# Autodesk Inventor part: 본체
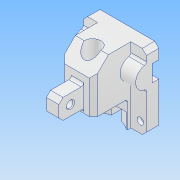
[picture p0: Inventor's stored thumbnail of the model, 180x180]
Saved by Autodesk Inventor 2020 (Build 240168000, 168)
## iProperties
Created: 2022-08
Part Number: 본체
Material: 알루미늄 6061
Document SubType Name: Modeling
Designer: user
Density: 2.7 g/cm^3
Appearance: 알루미늄 - 평지
Mass: 503.935 g
Surface Area: 335.341 cm^2
Volume: 186.643 cm^3
Author: user
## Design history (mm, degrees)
sketch "스케치1"
  geometry: L1 (38, 45)-(-38, 45); L2 (-38, 45)-(-38, -45); L3 (-38, -45)-(38, -45); L4 (38, -45)-(38, 45); L5 (38, 45)-(-38, -45); L6 (-38, 45)-(38, -45); 1 further point
  constraints: 12 end point, 2 midpoint, 2 parallel, 1 horizontal, 1 perpendicular
  dimensions: "d0" = 76 distance of L3.end L2.end; "d1" = 90 distance of L2.end L1.end
extrude "돌출1" new body sketch "스케치1" distance "d2" = 15; taper "d3" = 0 deg
sketch "스케치2"
  geometry: L1 (-38, -45)-(38, -45) reference; L2 (38, 45)-(-38, 45) reference; L3 (-20.765, 45)-(19.235, 45); L4 (19.235, 45)-(19.235, -13); L5 (19.235, -13)-(-20.765, -13); L6 (-20.765, -13)-(-20.765, 45); L7 (38, -45)-(38, 45) reference; 2 further points
  constraints: 8 end point, 2 parallel, 1 horizontal, 1 midpoint, 1 perpendicular, 1 point on line, 1 vertical alignment
  dimensions: "d4" = 32 distance between parallel lines of L1 L5; "d6" = 40 distance between parallel lines of L6 L4; "d7" = 18.76519 distance between parallel lines of L7 L4
extrude "돌출2" join sketch "스케치2" distance "d8" = 45; taper "d9" = 0 deg
sketch "스케치3"
  geometry: L1 (-20.765, -13)-(19.235, -13) reference; L2 (-7.5, 16)-(7.5, 16); L3 (7.5, 16)-(7.5, -8); L4 (7.5, -8)-(-7.5, -8); L5 (-7.5, -8)-(-7.5, 16); 2 further points
  constraints: 8 end point, 2 parallel, 1 horizontal, 1 midpoint, 1 perpendicular, 1 vertical alignment
  dimensions: "d10" = 5 distance between parallel lines of L1 L4; "d11" = 24 distance of L4.end L2.start; "d12" = 15 distance of L2.start L2.end
extrude "돌출3" join sketch "스케치3" distance "d13" = 30; taper "d14" = 0 deg
sketch "스케치4"
  geometry: L1 (15, 90)-(15, 0) reference; L2 (0, 90)-(15, 90) reference; C1 r 13 at (15, 63); 1 further point
  constraints: 1 centre point, 1 point on line
  dimensions: "d15" = 26 diameter of C1; "d16" = 27 distance from line of L2 C1.centre
extrude "돌출4" join sketch "스케치4" distance "d17" = 76; taper "d18" = 0 deg
sketch "스케치5"
  geometry: L1 (0, 90)-(0, 0) reference; L2 (8, 73)-(-8, 73); L3 (-8, 73)-(-8, 53); L4 (-8, 53)-(8, 53); L5 (8, 53)-(8, 73); L6 (8, 73)-(-8, 53); L7 (-8, 73)-(8, 53); A1 r 13 centre (15, 63) between (15, 50) and (15, 76) reference; 3 further points
  constraints: 12 end point, 3 midpoint, 2 parallel, 1 horizontal, 1 horizontal alignment, 1 perpendicular, 1 point on line
  dimensions: "d19" = 16 distance of L4.end L3.end; "d20" = 20 distance of L3.end L2.end
extrude "돌출5" cut sketch "스케치5" extent not by distance; stored distance "d21" = 0; taper "d22" = 0 deg
sketch "스케치6"
  geometry: L1 (-38, -45)-(38, -45) reference; L2 (19.235, -13)-(-20.765, -13); L3 (-20.765, -13)-(-20.765, -45); L4 (-20.765, -45)-(19.235, -45); L5 (19.235, -45)-(19.235, -13); 1 further point
  constraints: 8 end point, 2 parallel, 1 horizontal, 1 perpendicular, 1 point on line
extrude "돌출6" join sketch "스케치6" distance "d23" = 4; taper "d24" = 0 deg
sketch "스케치7"
  geometry: L1 (44, 19)-(32, 19); L2 (32, 19)-(32, -19); L3 (32, -19)-(44, -19); L4 (44, -19)-(44, 19); L5 (44, 19)-(32, -19); L6 (32, 19)-(44, -19); 1 further point
  constraints: 12 end point, 2 midpoint, 2 parallel, 1 horizontal, 1 perpendicular
  dimensions: "d25" = 12 distance of L3.end L2.end; "d26" = 38 distance of L2.end L1.end
extrude "돌출7" cut sketch "스케치7" distance "d27" = 18; taper "d28" = 0 deg
sketch "스케치8"
  geometry: C1 r 29 at (-38, 42); 1 further point
  constraints: 1 centre point, 1 vertical alignment
  dimensions: "d29" = 58 diameter of C1; "d30" = 42 distance of point (-38, 0) C1.centre
extrude "돌출8" cut sketch "스케치8" distance "d31" = 18; taper "d32" = 0 deg
sketch "스케치9"
  geometry: L1 (26.765, -60)-(14.765, -60) reference; C1 r 14.5 at (20.765, -18); 2 further points
  constraints: 1 centre point, 1 midpoint, 1 vertical alignment
  dimensions: "d33" = 29 diameter of C1; "d34" = 42 distance from line of L1 C1.centre
extrude "돌출9" cut sketch "스케치9" distance "d35" = 7; taper "d36" = 0 deg
sketch "스케치10"
  geometry: L1 (6, -42)-(-6, -42) reference; C1 r 14.5 at (0, 0); C2 r 10 at (0, 0); 2 further points
  constraints: 2 centre point, 1 coincident, 1 midpoint, 1 vertical alignment
  dimensions: "d37" = 20 diameter of C2; "d74" = 42 distance from line of L1 C1.centre
extrude "돌출10" cut sketch "스케치10" extent not by distance; stored distance "d38" = 0; taper "d39" = 0 deg
chamfer "모따기1" distance "d40" = 18; stored, may be unused: second distance "d41" = 2, angle "d42" = 45 deg
chamfer "모따기2" distance "d43" = 5; stored, may be unused: second distance "d44" = 2, angle "d45" = 45 deg
fillet "모깎기1" dims "d46" = 3
fillet "모깎기2" dims "d47" = 3
sketch "스케치11"
  geometry: L1 (-3, 90)-(11, 90) reference; L2 (-13, 22)-(-13, 60) reference; L3 (-13, 41)-(45, 41); L4 (45, 15)-(45, 42) reference; C1 r 4 at (4, 76); 2 further points
  constraints: 2 end point, 2 midpoint, 1 centre point, 1 horizontal, 1 point on line, 1 vertical alignment
  dimensions: "d48" = 8 diameter of C1; "d49" = 35 distance from line of C1.centre L3
extrude "돌출11" cut sketch "스케치11" extent not by distance; stored distance "d50" = 7.5; taper "d51" = 0 deg
chamfer "모따기3" distance "d52" = 1; stored, may be unused: second distance "d53" = 2, angle "d54" = 45 deg
chamfer "모따기4" distance "d55" = 1; stored, may be unused: second distance "d56" = 2, angle "d57" = 45 deg
sketch "스케치12"
  geometry: L1 (7, 32)-(45, 32) reference; L2 (45, 72)-(45, 32) reference; 2 further points
  constraints: 1 other
  dimensions: "d58" = 26 distance from line of point (27, 58) L1; "d59" = 18 distance from line of L2 point (27, 58)
feature "엠보싱1" sketch "스케치12" dims "d0" = 76, "d1" = 90, "d60" = 0.5, "d61" = 0
chamfer "모따기5" distance "d62" = 5; stored, may be unused: second distance "d63" = 2, angle "d64" = 45 deg
sketch "스케치13"
  geometry: L1 (-33, -45)-(-20.765, -45) reference; L2 (-38, 2.284)-(-20.765, 2.284) reference; 4 further points
  constraints: 1 horizontal alignment, 1 midpoint, 1 vertical alignment
  dimensions: "d65" = 13 distance from line of L1 point (-29.383, -32); "d66" = 60 distance of point (-29.383, -32) point (30.617, -32)
hole "구멍1" sketch "스케치13" at (-29.383, -32), (30.617, -32) diameter "d67" = 4.5; stored, may be unused: countersink angle "d71" = 90 deg, drill point angle "d73" = 118 deg; dims "d68" = 10, "d69" = 8, "d70" = 4.4, "d72" = 12
chamfer "모따기6" distance "d75" = 5; stored, may be unused: second distance "d76" = 2, angle "d77" = 45 deg
node "솔리드1"
feature "A9D066F2-1C7D-4E18-AEED-F7BC21143FA4" dims "d67" = 4.5, "d68" = 10, "d69" = 8, "d70" = 4.4, "d71" = 90 deg, "d72" = 12, "d73" = 118 deg
